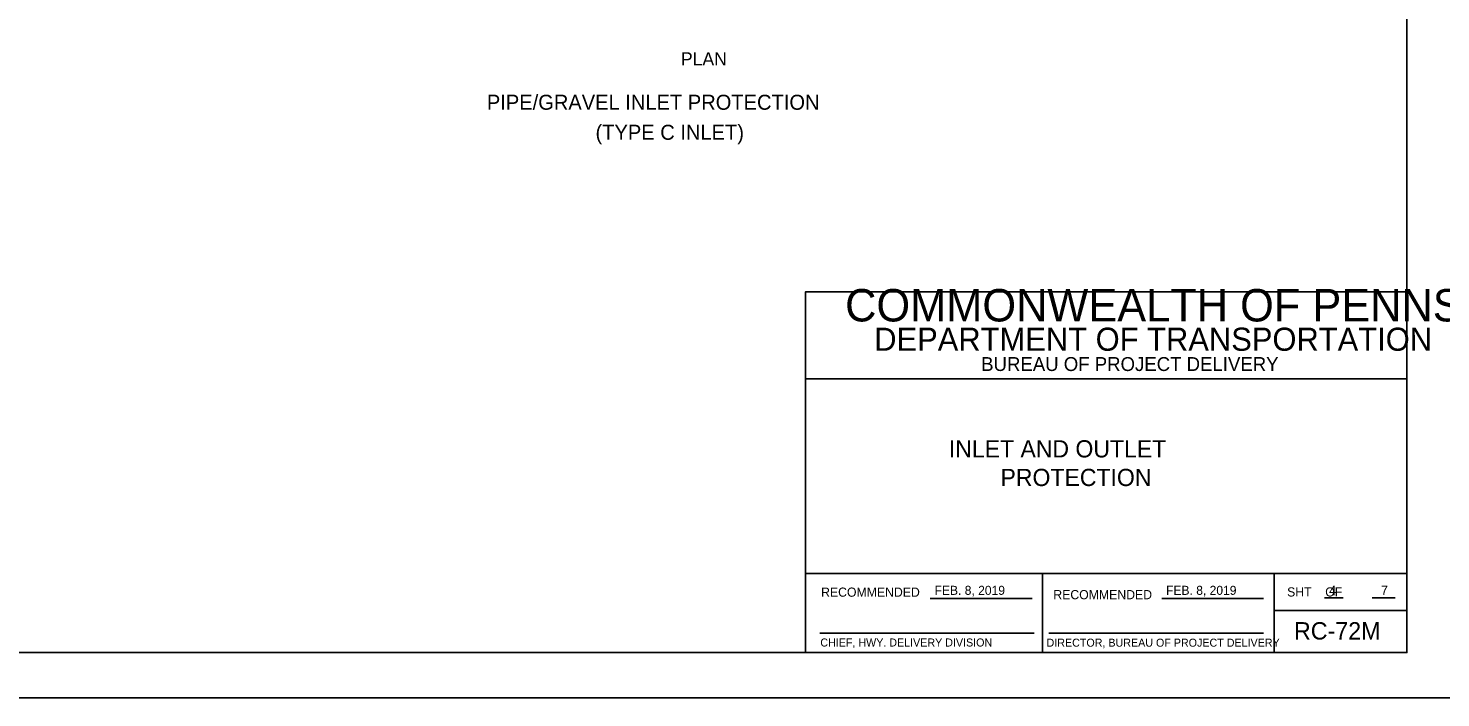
# Model space of a CAD drawing. Extents: x 636183 to 639890, y 299162 to 300538.
# Drawn here: x 637670.4 to 638140.2, y 299350.4 to 299573.1 of the extents above; entities that cross this region are included whole.
import ezdxf

# ---------------------------------------------------------------- set-up
doc = ezdxf.new("R2010")
doc.units = 0
for name, color, linetype in [('1', 7, 'Continuous'), ('Default', 7, 'Continuous'), ('PLT-BNDY', 7, 'Continuous')]:
    doc.layers.add(name, color=color, linetype=linetype)

msp = doc.modelspace()

# ---------------------------------------------------------------- linework, layer by layer
at = {"layer": '1'}
for p, q in [((637970.38, 299383.44), (638004.27, 299383.44)), ((638047.38, 299383.44), (638081.25, 299383.44)), ((638101.54, 299383.66), (638107.68, 299383.66)), ((638117.35, 299383.66), (638124.99, 299383.66)), ((637933.68, 299371.87), (638004.93, 299371.87)), ((638009.85, 299371.87), (638081.19, 299371.87))]:
    msp.add_line(p, q, dxfattribs=at)
msp.add_lwpolyline([(638128.91, 299365.45), (638128.91, 299929.45), (637342.91, 299929.45), (637342.91, 299365.45), (638128.91, 299365.45), (638128.91, 299391.81), (637928.91, 299391.81), (637928.91, 299456.49), (638128.91, 299456.49), (638128.91, 299485.45), (637928.91, 299485.45), (637928.91, 299365.45), (638007.72, 299365.45), (638007.72, 299391.81), (638007.72, 299365.45), (638084.72, 299365.45), (638084.72, 299391.81), (638084.72, 299379.49), (638128.91, 299379.49)], dxfattribs=at)
at = {"layer": 'PLT-BNDY'}
msp.add_lwpolyline([(637302.91, 299944.45), (638143.91, 299944.45), (638143.91, 299350.45), (637302.91, 299350.45)], close=True, dxfattribs=at)

# ---------------------------------------------------------------- texts
at = {"layer": '1'}
for s, height, p in [('COMMONWEALTH OF PENNSYLVANIA', 10.7834, (637942.07, 299475.59)), ('DEPARTMENT OF TRANSPORTATION', 7.6843, (637951.75, 299465.84)), ('BUREAU OF PROJECT DELIVERY', 4.6221, (637987.32, 299459.11)), ('RECOMMENDED', 3.048, (637934.08, 299384.04)), ('APPROVED', 0.0192, (637971.94, 299383.38)), ('APPROVED', 0.0192, (637971.94, 299383.38)), ('APPROVED', 0.0192, (637971.94, 299383.38)), ('APPROVED', 0.0192, (637971.94, 299383.38)), ('APPROVED', 0.0192, (637971.94, 299383.38)), ('APPROVED', 0.0192, (637971.94, 299383.38)), ('APPROVED', 0.0192, (637971.94, 299383.38)), ('APPROVED', 0.0192, (637971.94, 299383.38)), ('APPROVED', 0.0192, (637971.94, 299383.38)), ('APPROVED', 0.0192, (637971.94, 299383.38)), ('APPROVED', 0.0192, (637971.94, 299383.38)), ('APPROVED', 0.0192, (637971.94, 299383.38)), ('APPROVED', 0.0192, (637971.94, 299383.38)), ('APPROVED', 0.0192, (637971.94, 299383.38)), ('APPROVED', 0.0192, (637971.94, 299383.38)), ('APPROVED', 0.0192, (637971.94, 299383.38)), ('FEB. 8, 2019', 3, (637971.82, 299384.67)), ('RECOMMENDED', 3.048, (638011.32, 299383.21)), ('FEB. 8, 2019', 3, (638048.82, 299384.67)), ('SHT    OF', 3.048, (638089.08, 299384.12)), ('4', 3.13, (638103.05, 299384.54)), ('7', 3.13, (638120.28, 299384.59)), ('CHIEF, HWY. DELIVERY DIVISION', 2.6623, (637933.82, 299367.49)), ('DIRECTOR, BUREAU OF PROJECT DELIVERY', 2.6623, (638009.07, 299367.43))]:
    msp.add_text(s, height=height, dxfattribs=at).set_placement(p)
at = {"layer": 'Default'}
for s, height, p in [('PLAN', 4.372, (637887.46, 299560.73)), ('PIPE/GRAVEL INLET PROTECTION', 4.9967, (637822.91, 299545.99)), ('(TYPE C INLET)', 4.9967, (637859.05, 299536)), ('INLET AND OUTLET', 5.7257, (637976.56, 299430.37)), ('PROTECTION', 5.726, (637993.76, 299420.85)), ('RC-72M', 5.779, (638091.37, 299369.81))]:
    msp.add_text(s, height=height, dxfattribs=at).set_placement(p)

doc.saveas('drawing.dxf')
